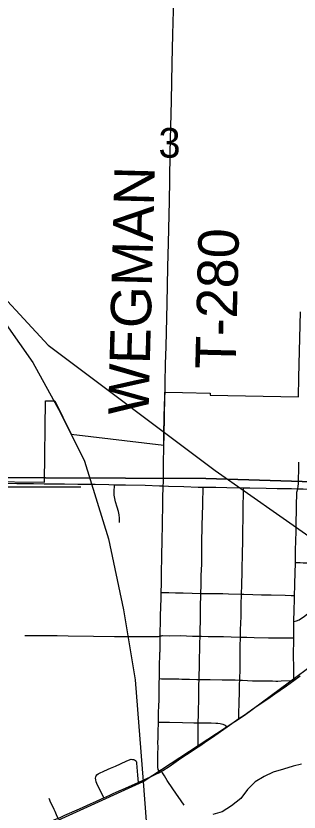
# Model space of a CAD drawing. Extents: x -8.3 to 42.1, y 0 to 22.
# Drawn here: x 5.164 to 5.562, y 16.882 to 18.005 of the extents above; entities that cross this region are included whole.
import ezdxf

# ---------------------------------------------------------------- set-up
doc = ezdxf.new("R2010")
doc.units = 0
for name, color, linetype in [('GM_X_City_Street', 7, 'Continuous'), ('GM_X_Corporation', 7, 'Continuous'), ('GM_X_Major_River', 7, 'Continuous'), ('GM_X_Minor_River', 7, 'Continuous'), ('GM_X_Rail_Line', 7, 'Continuous'), ('GM_X_Section', 7, 'Continuous'), ('GM_X_Section_Text', 7, 'Continuous'), ('GM_X_State_Route', 7, 'Continuous'), ('GM_X_Township_Road', 7, 'Continuous'), ('GM_X_Township_Road_Text', 7, 'Continuous')]:
    doc.layers.add(name, color=color, linetype=linetype)

msp = doc.modelspace()

# ---------------------------------------------------------------- linework, layer by layer
at = {"layer": 'GM_X_City_Street'}
for points in [[(5.5546, 17.0672), (5.5547, 17.0912), (5.5545, 17.0972), (5.5545, 17.1081), (5.5548, 17.1204), (5.5547, 17.1274), (5.5546, 17.1343), (5.5549, 17.1486), (5.5549, 17.1508), (5.5552, 17.1672), (5.5556, 17.1812), (5.5557, 17.1872), (5.5561, 17.2014), (5.5568, 17.2215), (5.557, 17.2307), (5.557, 17.2333), (5.5571, 17.24), (5.5573, 17.2539), (5.5575, 17.2617), (5.5579, 17.2803), (5.5586, 17.3176), (5.559, 17.3285), (5.5592, 17.3331), (5.5603, 17.3378), (5.561, 17.3415), (5.5612, 17.3446), (5.5618, 17.3711), (5.5618, 17.3754)], [(5.3094, 17.2903), (5.3092, 17.2965), (5.3088, 17.3011), (5.3079, 17.3057), (5.3061, 17.3117), (5.3038, 17.3192), (5.3027, 17.3239), (5.3019, 17.3286), (5.3017, 17.3334), (5.3018, 17.3357), (5.3021, 17.3407), (5.3023, 17.3435)], [(5.3657, 16.9379), (5.365, 16.9397), (5.364, 16.9421), (5.3632, 16.9452), (5.3632, 16.9492), (5.3632, 16.9539), (5.3634, 16.9585), (5.3635, 16.9642), (5.3636, 16.9735), (5.3635, 16.9798), (5.3637, 16.986), (5.3639, 16.9938), (5.3639, 16.9953), (5.3642, 17.0077), (5.3642, 17.0088), (5.3642, 17.014), (5.3644, 17.0201), (5.3649, 17.034), (5.3651, 17.0371), (5.3651, 17.0495), (5.3651, 17.051), (5.3652, 17.0618), (5.3653, 17.0649), (5.3655, 17.0701), (5.3656, 17.0711), (5.3655, 17.0773), (5.3656, 17.0851), (5.3662, 17.1068), (5.3664, 17.1083), (5.3665, 17.1099), (5.3664, 17.1114), (5.3665, 17.113), (5.3664, 17.1161), (5.3667, 17.1302), (5.3668, 17.1378), (5.367, 17.1472), (5.367, 17.1502), (5.3671, 17.158), (5.3676, 17.1717), (5.3679, 17.1828), (5.3681, 17.1884), (5.3682, 17.1916), (5.3684, 17.2041), (5.3686, 17.218), (5.3686, 17.2213), (5.3687, 17.2266), (5.3689, 17.2345), (5.369, 17.2405), (5.3691, 17.2505), (5.3693, 17.2585), (5.3694, 17.2616), (5.3694, 17.2646), (5.3695, 17.2692), (5.3699, 17.2832), (5.3701, 17.3002), (5.3702, 17.3049), (5.3703, 17.3078), (5.3704, 17.3155), (5.3703, 17.3186), (5.3705, 17.3235), (5.3708, 17.3418)], [(5.3708, 17.3418), (5.3784, 17.3413), (5.4001, 17.3409), (5.4202, 17.3402), (5.427, 17.3401), (5.445, 17.3399), (5.4604, 17.3397), (5.4841, 17.3392), (5.4929, 17.3391), (5.5161, 17.3387), (5.5315, 17.3384), (5.5392, 17.3383), (5.5516, 17.338), (5.5603, 17.3378)], [(5.4199, 16.9737), (5.42, 16.9827), (5.4201, 16.9929), (5.4203, 17.0077), (5.4206, 17.0195), (5.4208, 17.0257), (5.4211, 17.0396), (5.4212, 17.0473), (5.4213, 17.0519), (5.4213, 17.0579), (5.4213, 17.061), (5.4214, 17.0688), (5.422, 17.0919), (5.4222, 17.1011), (5.4223, 17.1088), (5.4225, 17.1196), (5.4228, 17.1299), (5.4228, 17.132), (5.4232, 17.1585), (5.4235, 17.1724), (5.4239, 17.1879), (5.4239, 17.1902), (5.4242, 17.2021), (5.4245, 17.2154), (5.4249, 17.2236), (5.4251, 17.2314), (5.4255, 17.2609), (5.4258, 17.2858), (5.4265, 17.3152), (5.4268, 17.3261), (5.427, 17.3307), (5.427, 17.3352), (5.427, 17.3401)], [(5.4775, 17.0136), (5.4775, 17.0178), (5.4774, 17.0238), (5.4778, 17.0331), (5.4779, 17.0394), (5.4781, 17.0481), (5.4785, 17.0623), (5.4788, 17.068), (5.4789, 17.0735), (5.4791, 17.079), (5.4791, 17.0867), (5.4792, 17.0915), (5.4793, 17.099), (5.4793, 17.1068), (5.4793, 17.1131), (5.4793, 17.1185), (5.4797, 17.1251), (5.4797, 17.1286), (5.4797, 17.1314), (5.4797, 17.136), (5.4798, 17.139), (5.4802, 17.1483), (5.4805, 17.1575), (5.4805, 17.1637), (5.4807, 17.1668), (5.4808, 17.173), (5.4809, 17.1792), (5.4811, 17.1839), (5.4811, 17.187), (5.4812, 17.1891), (5.4815, 17.2025), (5.4818, 17.2072), (5.4819, 17.216), (5.4822, 17.2215), (5.4822, 17.2266), (5.4823, 17.2315), (5.4824, 17.2389), (5.4826, 17.2451), (5.4826, 17.2516), (5.4829, 17.2588), (5.483, 17.2669), (5.4832, 17.2803), (5.4833, 17.2947), (5.4834, 17.3008), (5.4834, 17.3024), (5.4834, 17.3054), (5.4834, 17.3077), (5.4834, 17.3107), (5.4834, 17.3138), (5.4835, 17.3169), (5.4836, 17.3185), (5.4836, 17.32), (5.4838, 17.3246), (5.4839, 17.3276), (5.4839, 17.333), (5.484, 17.3368), (5.4841, 17.3392)], [(5.5603, 17.3378), (5.568, 17.3376), (5.5774, 17.3374), (5.5867, 17.3372), (5.5976, 17.337), (5.6256, 17.3364), (5.6442, 17.336), (5.6691, 17.3355), (5.6881, 17.3354), (5.7096, 17.335), (5.7208, 17.3348), (5.7406, 17.3346), (5.7529, 17.3344), (5.7577, 17.3343), (5.7764, 17.3337), (5.7845, 17.3336), (5.8028, 17.3334), (5.8262, 17.3331), (5.8479, 17.3327), (5.8651, 17.3325), (5.8736, 17.3323)], [(5.6493, 17.1381), (5.6446, 17.1446), (5.6373, 17.1545), (5.628, 17.1669), (5.62, 17.1782), (5.6119, 17.1894), (5.6082, 17.1945), (5.6036, 17.2007), (5.597, 17.2092), (5.5859, 17.2241), (5.5823, 17.2291), (5.5813, 17.2303), (5.5801, 17.2312), (5.5788, 17.232), (5.5774, 17.2325), (5.5759, 17.2328), (5.5728, 17.2331), (5.5713, 17.233), (5.5682, 17.2331), (5.5638, 17.2332), (5.561, 17.2332), (5.557, 17.2333)], [(5.3682, 17.1916), (5.3707, 17.1916), (5.379, 17.1914), (5.3882, 17.1911), (5.3992, 17.191), (5.4118, 17.1906), (5.4239, 17.1902), (5.4272, 17.1901), (5.4439, 17.19), (5.4547, 17.1899), (5.463, 17.1898), (5.4812, 17.1891), (5.4842, 17.189), (5.4969, 17.1888), (5.5092, 17.1884), (5.5231, 17.1881), (5.5426, 17.1877), (5.551, 17.1873), (5.5557, 17.1872)], [(5.5549, 17.1508), (5.5585, 17.1516), (5.5623, 17.1532), (5.5671, 17.1564), (5.5679, 17.1569), (5.5758, 17.163), (5.5844, 17.1696), (5.5931, 17.1757), (5.5983, 17.1797), (5.602, 17.1824), (5.6098, 17.1878), (5.6119, 17.1894)], [(5.176, 17.1309), (5.1847, 17.1309), (5.1982, 17.1309), (5.2214, 17.1307), (5.2369, 17.1303), (5.2728, 17.1298), (5.3021, 17.1295), (5.3222, 17.1297), (5.333, 17.1297), (5.3516, 17.1293), (5.3614, 17.1293), (5.363, 17.1294), (5.3642, 17.1295), (5.3667, 17.1302), (5.3686, 17.1306), (5.3693, 17.1307), (5.3701, 17.1307), (5.3797, 17.1306), (5.3952, 17.1307), (5.4123, 17.1301), (5.4228, 17.1299), (5.4248, 17.1299), (5.434, 17.1297), (5.4448, 17.1295), (5.4479, 17.1295), (5.4556, 17.1293), (5.4664, 17.129), (5.4797, 17.1286), (5.4834, 17.1285), (5.4885, 17.1284), (5.4991, 17.1282), (5.5193, 17.1278), (5.5285, 17.1277), (5.533, 17.1277), (5.5423, 17.1274), (5.5518, 17.1274), (5.5547, 17.1274)], [(5.3655, 17.0701), (5.3686, 17.07), (5.3773, 17.0699), (5.3852, 17.0698), (5.3928, 17.0697), (5.397, 17.0694), (5.4016, 17.0693), (5.4077, 17.0692), (5.4184, 17.069), (5.4214, 17.0688), (5.423, 17.0688), (5.4276, 17.0687), (5.4307, 17.0687), (5.4369, 17.0686), (5.4538, 17.0685), (5.4676, 17.0685), (5.4723, 17.0683), (5.4788, 17.068), (5.4825, 17.0677), (5.4968, 17.0671), (5.5247, 17.0668), (5.5293, 17.0667), (5.5322, 17.0667), (5.5372, 17.0668), (5.5546, 17.0672)], [(5.3642, 17.0088), (5.3669, 17.0087), (5.3798, 17.0085), (5.3982, 17.0082), (5.4138, 17.0079), (5.4203, 17.0077), (5.4293, 17.0075), (5.4386, 17.0075), (5.4448, 17.0073), (5.4479, 17.0071), (5.4513, 17.0066), (5.4548, 17.0059), (5.458, 17.0045), (5.4611, 17.0022)], [(5.2872, 16.902), (5.2811, 16.9144), (5.2785, 16.9199), (5.2766, 16.9245), (5.2759, 16.9273), (5.2757, 16.9299), (5.2759, 16.9317), (5.2764, 16.933), (5.2775, 16.9344), (5.2791, 16.9357), (5.2822, 16.9373), (5.2862, 16.9392), (5.2934, 16.9424), (5.2965, 16.9438), (5.3036, 16.9468), (5.3188, 16.9537), (5.3246, 16.956), (5.326, 16.9563), (5.3275, 16.9562), (5.3291, 16.956), (5.3306, 16.9556), (5.3319, 16.9548), (5.3328, 16.9536), (5.3333, 16.9522), (5.3335, 16.9506), (5.3348, 16.9337), (5.3356, 16.9237)], [(5.4002, 16.8915), (5.3846, 16.9146), (5.3765, 16.9263), (5.3726, 16.9329), (5.3709, 16.9357), (5.3687, 16.9394)], [(5.2228, 16.873), (5.2206, 16.8781), (5.2187, 16.8825), (5.2174, 16.8853), (5.2155, 16.8895), (5.2128, 16.8951), (5.2102, 16.9009)]]:
    msp.add_lwpolyline(points, dxfattribs=at)
at = {"layer": 'GM_X_Corporation'}
msp.add_lwpolyline([(5.1193, 17.3479), (5.2037, 17.3472), (5.2053, 17.4618), (5.2182, 17.4617), (5.2414, 17.4147), (5.3717, 17.3992), (5.3718, 17.4138), (5.3723, 17.4403), (5.3732, 17.4681), (5.3732, 17.4741), (5.3983, 17.4734), (5.437, 17.4727), (5.4369, 17.47), (5.5616, 17.4673), (5.5621, 17.4948), (5.5642, 17.5875)], dxfattribs=at)
at = {"layer": 'GM_X_Major_River'}
msp.add_lwpolyline([(5.5658, 16.9492), (5.554, 16.9464), (5.5402, 16.9426), (5.5257, 16.938), (5.5131, 16.9319), (5.5004, 16.9246), (5.4895, 16.9135), (5.4801, 16.9012), (5.467, 16.8905), (5.4539, 16.8824), (5.4409, 16.8786)], dxfattribs=at)
at = {"layer": 'GM_X_Minor_River'}
msp.add_lwpolyline([(3.8877, 17.315), (4.0396, 17.3152), (4.2494, 17.3165), (4.4745, 17.3232), (4.749, 17.334), (4.9161, 17.3399), (5.0801, 17.3405), (5.2547, 17.3408)], dxfattribs=at)
at = {"layer": 'GM_X_Rail_Line'}
for points in [[(4.1842, 20.9), (4.2824, 20.3978), (4.5315, 19.127), (4.6541, 18.5101), (4.7015, 18.2399), (4.7193, 18.1628), (4.7437, 18.1035), (4.7782, 18.045), (4.9031, 17.884), (5.1089, 17.6286), (5.1497, 17.5693), (5.1874, 17.5157), (5.2262, 17.4447), (5.2601, 17.3769), (5.294, 17.2671), (5.315, 17.167), (5.3312, 17.0685), (5.3428, 16.9248)], [(4.4602, 20.9), (4.4279, 19.896), (4.4279, 19.7141), (4.5329, 19.1719), (4.7134, 18.2287), (4.7298, 18.1615), (4.7562, 18.1061), (4.7924, 18.0389), (4.852, 17.9646), (5.1115, 17.6457), (5.209, 17.5403), (5.4439, 17.3636), (5.6263, 17.2359), (5.6901, 17.1722)], [(5.3428, 16.9248), (5.4853, 17.0187), (5.6464, 17.1381), (5.6901, 17.1722)], [(3.5481, 16.7901), (3.5751, 16.7924), (3.642, 16.7979), (3.7302, 16.7871), (4.0849, 16.6622), (4.2594, 16.6204), (4.3265, 16.61), (4.5771, 16.6383), (4.6964, 16.6517), (4.847, 16.6995), (5.3428, 16.9248)], [(5.3428, 16.9248), (5.3604, 16.689), (5.3556, 16.5985), (5.3541, 16.4612), (5.3493, 16.2965), (5.3382, 15.8766), (5.3398, 15.8056), (5.3447, 15.7232), (5.3447, 15.6312), (5.3415, 15.5213), (5.3256, 14.9739), (5.302, 14.1)]]:
    msp.add_lwpolyline(points, dxfattribs=at)
at = {"layer": 'GM_X_Section'}
for points in [[(4.9147, 18.3251), (5.8932, 18.3221), (5.8682, 17.3386), (5.431, 17.3522), (4.866, 17.3546), (4.8893, 18.3249)], [(5.8682, 17.3386), (5.8503, 16.3424), (4.8464, 16.3395), (4.866, 17.3546), (5.431, 17.3522)]]:
    msp.add_lwpolyline(points, close=True, dxfattribs=at)
at = {"layer": 'GM_X_State_Route'}
for points in [[(5.3519, 16.931), (5.3597, 16.9347), (5.3657, 16.9379), (5.3687, 16.9394), (5.3705, 16.9404), (5.3794, 16.9462), (5.3857, 16.9507), (5.3959, 16.9577), (5.4035, 16.9629), (5.4073, 16.9654), (5.4175, 16.9721), (5.4199, 16.9737), (5.4238, 16.9763), (5.4289, 16.9798), (5.4403, 16.9877), (5.4517, 16.9956), (5.4611, 17.0022), (5.4707, 17.0089), (5.4775, 17.0136), (5.4847, 17.0186), (5.4987, 17.0285), (5.518, 17.0415), (5.5282, 17.0485), (5.5447, 17.0601), (5.5546, 17.0672), (5.5636, 17.0741)], [(5.1589, 16.8442), (5.1715, 16.8501), (5.1828, 16.8552), (5.2025, 16.8642), (5.2209, 16.8722), (5.2228, 16.873), (5.2326, 16.8773), (5.2531, 16.8864), (5.2686, 16.8933), (5.2769, 16.8974), (5.284, 16.9005), (5.2872, 16.902), (5.2956, 16.9059), (5.3006, 16.908), (5.3091, 16.9116), (5.3176, 16.9154), (5.3316, 16.9218), (5.3356, 16.9237), (5.3499, 16.9301), (5.3519, 16.931)]]:
    msp.add_lwpolyline(points, dxfattribs=at)
at = {"layer": 'GM_X_Township_Road'}
for points in [[(5.3735, 17.4736), (5.3737, 17.4871), (5.3742, 17.5136), (5.375, 17.5384), (5.3764, 17.599), (5.3775, 17.6503), (5.3784, 17.6845), (5.3797, 17.7436), (5.3803, 17.7731), (5.3809, 17.812), (5.3825, 17.885), (5.3836, 17.9379), (5.3846, 17.9783), (5.3854, 18.0125), (5.3871, 18.0809), (5.3876, 18.1073), (5.3881, 18.126), (5.389, 18.1508), (5.3903, 18.2146), (5.3912, 18.2472), (5.3926, 18.2938), (5.393, 18.3032), (5.3933, 18.3114)], [(5.3719, 17.3986), (5.3721, 17.4132), (5.3725, 17.4398), (5.3734, 17.4675), (5.3735, 17.4736)], [(5.3708, 17.3418), (5.3711, 17.3468), (5.3712, 17.3531), (5.3713, 17.3627), (5.3715, 17.3797), (5.3717, 17.3908), (5.3719, 17.3986)], [(5.1195, 17.346), (5.165, 17.3454), (5.1882, 17.3451), (5.2031, 17.345), (5.2091, 17.345), (5.2219, 17.3448)], [(5.2219, 17.3448), (5.2318, 17.3447), (5.2505, 17.3444), (5.2616, 17.3443), (5.2626, 17.3442)], [(5.2626, 17.3442), (5.2695, 17.3442), (5.275, 17.3441)], [(5.275, 17.3441), (5.2942, 17.3437), (5.3023, 17.3435)], [(5.3023, 17.3435), (5.3176, 17.3433), (5.3457, 17.3429), (5.3659, 17.342), (5.3708, 17.3418)]]:
    msp.add_lwpolyline(points, dxfattribs=at)

# ---------------------------------------------------------------- texts
at = {"layer": 'GM_X_Section_Text'}
msp.add_text('3', height=0.0419, rotation=0, dxfattribs=at).set_placement((5.3642, 17.8048))
at = {"layer": 'GM_X_Township_Road_Text'}
for s, rotation, p in [('WEGMAN', 88.5149, (5.3502, 17.4415)), ('T-280', 88.5959, (5.4728, 17.5061))]:
    msp.add_text(s, height=0.05682, rotation=rotation, dxfattribs=at).set_placement(p)

doc.saveas('drawing.dxf')
